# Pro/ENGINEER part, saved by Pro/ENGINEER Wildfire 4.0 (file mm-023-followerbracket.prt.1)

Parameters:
  METRIC = "NO"

Other parameters: PITCH, DRILL_POINT_ANGLE, DRILL_DEPTH, DRILL_DIAMETER, THREAD_DIAMETER, THREADS_PER_INCH, THREAD_DEPTH, THREAD_LENGTH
